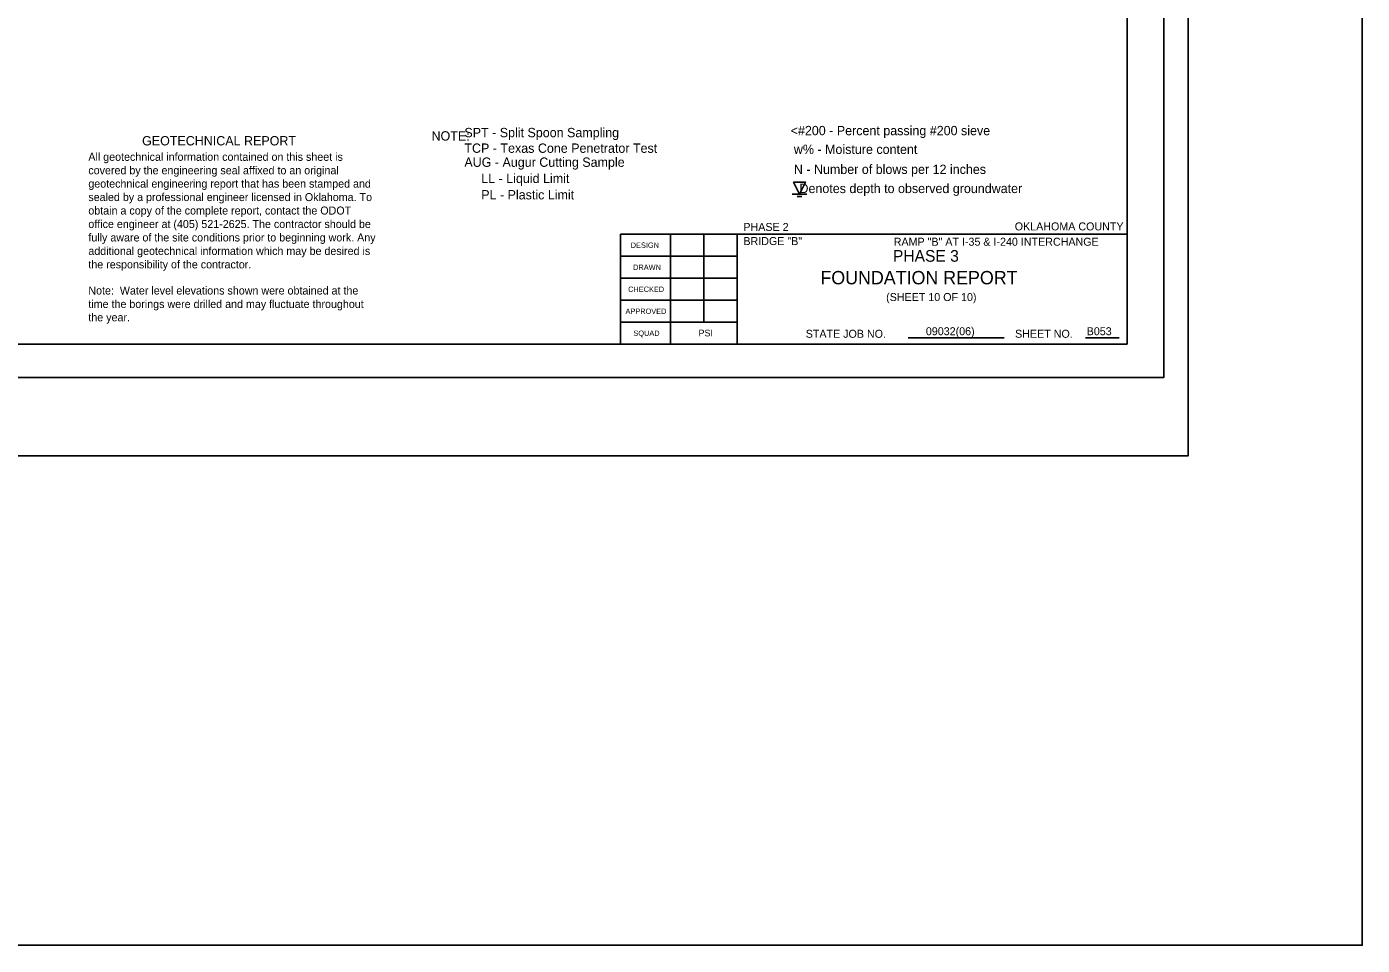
# Model space of a CAD drawing. Extents: x 2150162 to 2150245, y 143729 to 143865.
# Drawn here: x 2150225.21 to 2150245.24, y 143729.32 to 143743.1 of the extents above; entities that cross this region are included whole.
import ezdxf

# ---------------------------------------------------------------- set-up
doc = ezdxf.new("R2010")
doc.units = 0
for name, color, linetype in [('Default', 7, 'Continuous'), ('S', 7, 'Continuous'), ('SHT_Plot_Shape_Full', 7, 'Continuous'), ('SHT_Plot_Shape_Half', 7, 'Continuous'), ('SHT_Sheet_Border', 7, 'Continuous'), ('SHT_Standard_Sheet_Lines', 7, 'Continuous'), ('SHT_Standard_Sheet_Txt', 7, 'Continuous'), ('T', 7, 'Continuous'), ('T-Title', 7, 'Continuous'), ('Text', 7, 'Continuous')]:
    doc.layers.add(name, color=color, linetype=linetype)

# ---------------------------------------------------------------- blocks, each defined once
blk = doc.blocks.new('DGRFC_WTLEV1')
at = {"layer": 'Default'}
for points in [[(-0.0127, 0), (0.0127, 0)], [(0, 0), (0.0106, 0.0212), (-0.0106, 0.0212), (0, 0)], [(-0.0042, -0.0042), (0.0042, -0.0042)]]:
    blk.add_lwpolyline(points, dxfattribs=at)

msp = doc.modelspace()

# ---------------------------------------------------------------- linework, layer by layer
at = {"layer": 'S'}
msp.add_lwpolyline([(2150203.404, 143865.061), (2150245.24, 143865.061), (2150245.24, 143729.315), (2150203.404, 143729.315)], close=True, dxfattribs=at)
at = {"layer": 'SHT_Plot_Shape_Full'}
msp.add_lwpolyline([(2150206.628, 143760.659), (2150242.628, 143760.659), (2150242.628, 143736.659), (2150206.628, 143736.659)], close=True, dxfattribs=at)
at = {"layer": 'SHT_Plot_Shape_Half'}
msp.add_lwpolyline([(2150208.265, 143759.835), (2150242.265, 143759.835), (2150242.265, 143737.835), (2150208.265, 143737.835)], close=True, dxfattribs=at)
at = {"layer": 'SHT_Sheet_Border'}
for p, q in [((2150234.115, 143738.334), (2150234.115, 143739.985)), ((2150234.115, 143739.985), (2150241.715, 143739.985)), ((2150235.865, 143738.334), (2150235.865, 143739.985))]:
    msp.add_line(p, q, dxfattribs=at)
msp.add_lwpolyline([(2150241.715, 143738.334), (2150210.215, 143738.334), (2150210.215, 143759.335), (2150241.715, 143759.335)], close=True, dxfattribs=at)
at = {"layer": 'SHT_Standard_Sheet_Lines'}
for p, q in [((2150234.865, 143738.334), (2150234.865, 143739.985)), ((2150235.365, 143738.665), (2150235.365, 143739.985)), ((2150238.426, 143738.431), (2150239.866, 143738.431)), ((2150241.09, 143738.431), (2150241.593, 143738.431))]:
    msp.add_line(p, q, dxfattribs=at)
for points in [[(2150235.865, 143739.655), (2150234.115, 143739.655)], [(2150235.865, 143739.325), (2150234.115, 143739.325)], [(2150235.865, 143738.995), (2150234.115, 143738.995)], [(2150235.865, 143738.665), (2150234.115, 143738.665)]]:
    msp.add_lwpolyline(points, dxfattribs=at)

# ---------------------------------------------------------------- block references
at = {"layer": 'Default', "xscale": 8.503919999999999, "yscale": 8.503919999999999}
msp.add_blockref('DGRFC_WTLEV1', (2150236.799, 143740.585), dxfattribs=at)

# ---------------------------------------------------------------- texts
at = {"layer": 'Defpoints'}
msp.add_text('PHASE 3', height=0.175, dxfattribs=at).set_placement((2150238.2, 143739.572))
at = {"layer": 'SHT_Standard_Sheet_Txt'}
for s, height, p in [('DESIGN', 0.08, (2150234.267, 143739.78)), ('DRAWN', 0.08, (2150234.303, 143739.449)), ('CHECKED', 0.08, (2150234.228, 143739.119)), ('APPROVED', 0.08, (2150234.189, 143738.789)), ('SQUAD', 0.08, (2150234.307, 143738.459)), ('STATE JOB NO.', 0.12, (2150236.892, 143738.431)), ('SHEET NO. ', 0.12, (2150240.032, 143738.431))]:
    msp.add_text(s, height=height, dxfattribs=at).set_placement(p)
at = {"layer": 'T'}
for s, height, p in [('PHASE 2', 0.12, (2150235.957, 143740.034)), ('OKLAHOMA COUNTY', 0.12, (2150240.027, 143740.042)), ('BRIDGE "B"', 0.12, (2150235.957, 143739.822)), ('RAMP "B" AT I-35 & I-240 INTERCHANGE', 0.12, (2150238.212, 143739.812)), ('(SHEET 10 OF 10)', 0.12, (2150238.098, 143738.982)), ('PSI', 0.1, (2150235.284, 143738.452)), ('09032(06)', 0.12, (2150238.694, 143738.469)), ('B053', 0.12, (2150241.106, 143738.469))]:
    msp.add_text(s, height=height, dxfattribs=at).set_placement(p)
at = {"layer": 'T-Title'}
msp.add_text('FOUNDATION REPORT', height=0.2, dxfattribs=at).set_placement((2150237.112, 143739.233))
at = {"layer": 'Text'}
for s, height, p in [('NOTE:', 0.14, (2150231.279, 143741.39)), ('    SPT - Split Spoon Sampling', 0.14, (2150231.564, 143741.44)), (' <#200 - Percent passing #200 sieve', 0.14, (2150236.614, 143741.47)), ('GEOTECHNICAL REPORT', 0.14, (2150226.938, 143741.317)), ('    TCP - Texas Cone Penetrator Test', 0.14, (2150231.564, 143741.206)), ('w% - Moisture content', 0.14, (2150236.714, 143741.189)), ('All geotechnical information contained on this sheet is ', 0.12, (2150226.132, 143741.086)), ('    AUG - Augur Cutting Sample', 0.14, (2150231.564, 143740.996)), ('covered by the engineering seal affixed to an original ', 0.12, (2150226.132, 143740.884)), (' LL - Liquid Limit', 0.14, (2150231.973, 143740.753)), ('N - Number of blows per 12 inches', 0.14, (2150236.714, 143740.889)), ('geotechnical engineering report that has been stamped and ', 0.12, (2150226.132, 143740.684)), ('    Denotes depth to observed groundwater', 0.14, (2150236.59, 143740.602)), ('sealed by a professional engineer licensed in Oklahoma. To ', 0.12, (2150226.132, 143740.482)), (' PL - Plastic Limit', 0.14, (2150231.973, 143740.507)), ('obtain a copy of the complete report, contact the ODOT ', 0.12, (2150226.132, 143740.28)), ('office engineer at (405) 521-2625. The contractor should be ', 0.12, (2150226.132, 143740.078)), ('fully aware of the site conditions prior to beginning work. Any ', 0.12, (2150226.132, 143739.876)), ('additional geotechnical information which may be desired is ', 0.12, (2150226.132, 143739.674)), ('the responsibility of the contractor.', 0.12, (2150226.132, 143739.472)), ('Note:  Water level elevations shown were obtained at the ', 0.12, (2150226.132, 143739.08)), ('time the borings were drilled and may fluctuate throughout ', 0.12, (2150226.132, 143738.878)), ('the year.', 0.12, (2150226.132, 143738.678))]:
    msp.add_text(s, height=height, dxfattribs=at).set_placement(p)

doc.saveas('drawing.dxf')
